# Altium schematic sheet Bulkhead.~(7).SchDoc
size B; Organization: Monterey Bay Aquarium Research Institute; Address1: 7700 Sandholdt Rd; Address2: Moss Landing, CA 95039-9644; CompanyName: MBARI
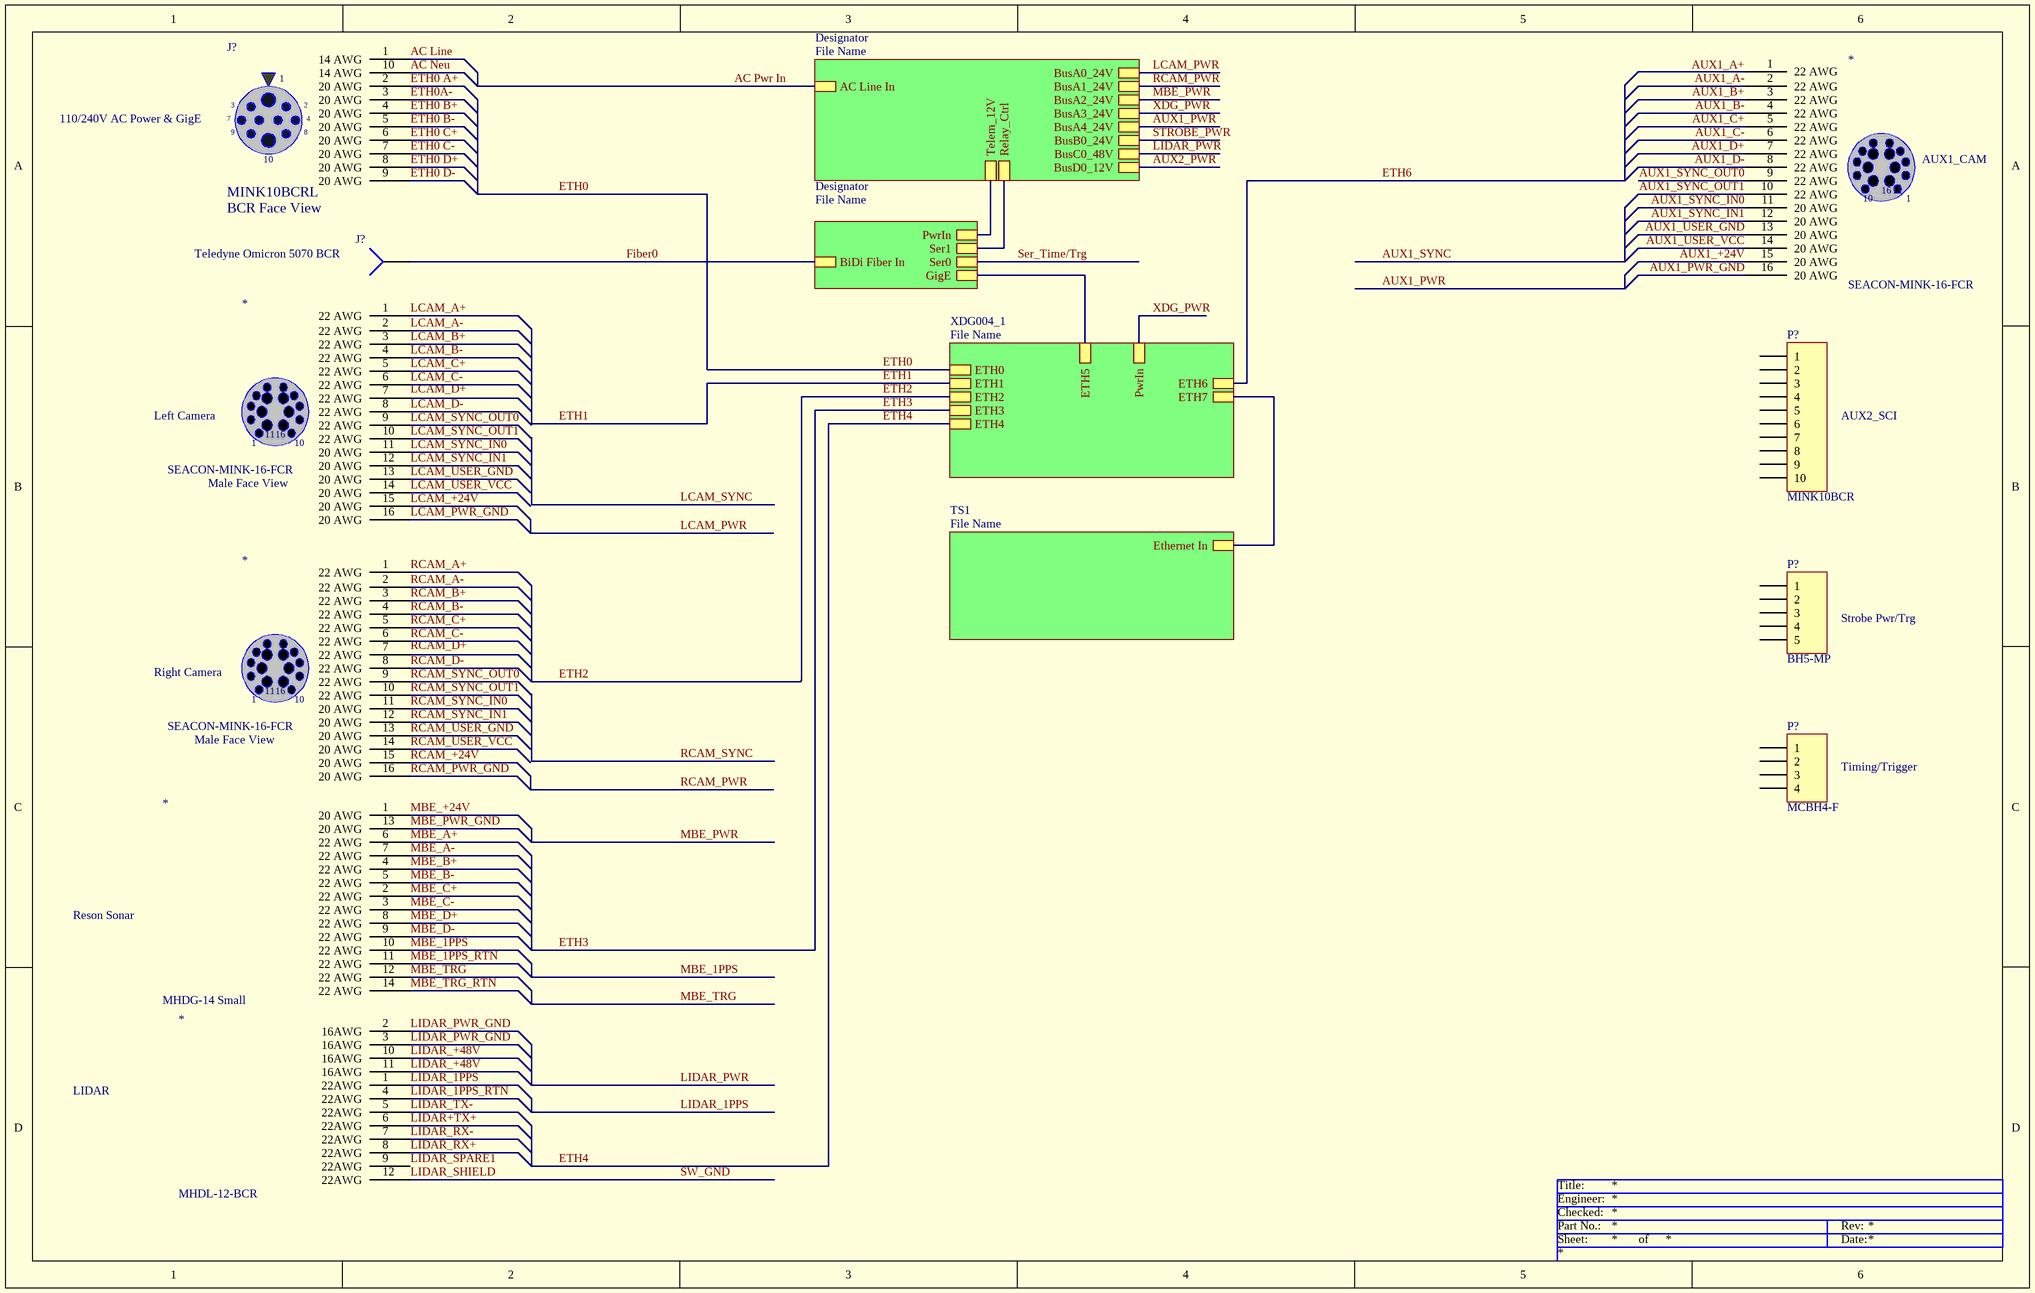
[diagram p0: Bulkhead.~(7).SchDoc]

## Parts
(Parts that share a designator on the sheet are numbered #1, #2 ... from top to bottom, then left to right.)
*#1  SEACON-MINK-16-FCR
*#2  SEACON-MINK-16-FCR
*#3  SEACON-MINK-16-FCR
*#4  MHDG-14 Small
*#5  MHDL-12-BCR
J?#1  MINK10BCRL  View: BCR Face View
J?#2  Teledyne Omicron 5070 BCR  [PIN1]
P?#1  MINK10BCR  [HDR1X10]
P?#2  BH5-MP  [HDR1X5]
P?#3  MCBH4-F  [HDR1X4]

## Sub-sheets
Designator = File Name: AC Line In, BusA0_24V, BusA1_24V, BusC0_48V, BusA2_24V, BusB0_24V, BusD0_12V, BusA3_24V, Telem_12V, Relay_Ctrl, BusA4_24V
Designator = File Name: BiDi Fiber In, GigE, Ser0, Ser1, PwrIn
TS1 = File Name: Ethernet In
XDG004_1 = File Name: ETH0, ETH1, ETH2, ETH3, ETH4, ETH5, ETH6, ETH7, PwrIn

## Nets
AC Line: J?#1.1(14_AWG)
AC Neu: J?#1.10(14_AWG)
AUX1_+24V: *#1.15(20_AWG)
AUX1_A-: *#1.2(22_AWG)
AUX1_B+: *#1.3(22_AWG)
AUX1_B-: *#1.4(22_AWG)
AUX1_C+: *#1.5(22_AWG)
AUX1_C-: *#1.6(22_AWG)
AUX1_D+: *#1.7(22_AWG)
AUX1_D-: *#1.8(22_AWG)
AUX1_PWR_GND: *#1.16(20_AWG)
AUX1_SYNC_IN0: *#1.11(20_AWG)
AUX1_SYNC_IN1: *#1.12(20_AWG)
AUX1_SYNC_OUT0: *#1.9(22_AWG)
AUX1_SYNC_OUT1: *#1.10(22_AWG)
AUX1_USER_GND: *#1.13(20_AWG)
AUX1_USER_VCC: *#1.14(20_AWG)
ETH0 A+: J?#1.2(20_AWG)
ETH0 B+: J?#1.4(20_AWG)
ETH0 B-: J?#1.5(20_AWG)
ETH0 C+: J?#1.6(20_AWG)
ETH0 C-: J?#1.7(20_AWG)
ETH0 D+: J?#1.8(20_AWG)
ETH0 D-: J?#1.9(20_AWG)
ETH0A-: J?#1.3(20_AWG)
Fiber0: J?#2.1 ; sheet Designator/BiDi Fiber In
LCAM_+24V: *#2.15(20_AWG)
LCAM_A+: *#2.1(22_AWG)
LCAM_A-: *#2.2(22_AWG)
LCAM_B+: *#2.3(22_AWG)
LCAM_B-: *#2.4(22_AWG)
LCAM_C+: *#2.5(22_AWG)
LCAM_C-: *#2.6(22_AWG)
LCAM_D-: *#2.8(22_AWG)
LCAM_PWR_GND: *#2.16(20_AWG)
LCAM_SYNC_IN0: *#2.11(20_AWG)
LCAM_SYNC_IN1: *#2.12(20_AWG)
LCAM_SYNC_OUT0: *#2.9(22_AWG)
LCAM_SYNC_OUT1: *#2.10(22_AWG)
LCAM_USER_GND: *#2.13(20_AWG)
LCAM_USER_VCC: *#2.14(20_AWG)
LIDAR+TX+: *#5.6(22AWG)
LIDAR_1PPS: *#5.1(22AWG)
LIDAR_1PPS_RTN: *#5.4(22AWG)
LIDAR_+48V: *#5.10(16AWG) *#5.11(16AWG)
LIDAR_PWR_GND: *#5.2(16AWG) *#5.3(16AWG)
LIDAR_RX+: *#5.8(22AWG)
LIDAR_RX-: *#5.7(22AWG)
LIDAR_SHIELD: *#5.12(22AWG)  [also labelled SW_GND]
LIDAR_SPARE1: *#5.9(22AWG)
LIDAR_TX-: *#5.5(22AWG)
MBE_1PPS: *#4.10(22_AWG)
MBE_1PPS_RTN: *#4.11(22_AWG)
MBE_+24V: *#4.1(20_AWG)
MBE_A+: *#4.6(22_AWG)
MBE_A-: *#4.7(22_AWG)
MBE_B+: *#4.4(22_AWG)
MBE_B-: *#4.5(22_AWG)
MBE_C+: *#4.2(22_AWG)
MBE_C-: *#4.3(22_AWG)
MBE_D+: *#4.8(22_AWG)
MBE_D-: *#4.9(22_AWG)
MBE_PWR_GND: *#4.13(20_AWG)
MBE_TRG: *#4.12(22_AWG)
MBE_TRG_RTN: *#4.14(22_AWG)
RCAM_+24V: *#3.15(20_AWG)
RCAM_A+: *#3.1(22_AWG)
RCAM_A-: *#3.2(22_AWG)
RCAM_B+: *#3.3(22_AWG)
RCAM_B-: *#3.4(22_AWG)
RCAM_C+: *#3.5(22_AWG)
RCAM_C-: *#3.6(22_AWG)
RCAM_D-: *#3.8(22_AWG)
RCAM_PWR_GND: *#3.16(20_AWG)
RCAM_SYNC_IN0: *#3.11(20_AWG)
RCAM_SYNC_IN1: *#3.12(20_AWG)
RCAM_SYNC_OUT0: *#3.9(22_AWG)
RCAM_SYNC_OUT1: *#3.10(22_AWG)
RCAM_USER_GND: *#3.13(20_AWG)
RCAM_USER_VCC: *#3.14(20_AWG)

Not connected (* = marked no-connect by the designer): *#1 1(22_AWG); *#2 7(22_AWG); *#3 7(22_AWG); P?#1 1 2 3 4 5 6 7 8 9 10; P?#2 1 2 3 4 5; P?#3 1 2 3 4

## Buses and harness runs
bus AC Pwr In = sheet Designator/AC Line In
bus AUX1_PWR
bus AUX1_PWR = sheet Designator/BusA4_24V
bus AUX1_SYNC
bus AUX2_PWR = sheet Designator/BusD0_12V
bus ETH0 = sheet XDG004_1/ETH0
bus ETH1 = sheet XDG004_1/ETH1
bus ETH2 = sheet XDG004_1/ETH2
bus ETH3 = sheet XDG004_1/ETH3
bus ETH4 = sheet XDG004_1/ETH4
bus ETH6 = sheet XDG004_1/ETH6
bus LCAM_PWR
bus LCAM_PWR = sheet Designator/BusA0_24V
bus LCAM_SYNC
bus LIDAR_1PPS
bus LIDAR_PWR
bus LIDAR_PWR = sheet Designator/BusC0_48V
bus MBE_1PPS
bus MBE_PWR
bus MBE_PWR = sheet Designator/BusA2_24V
bus MBE_TRG
bus RCAM_PWR
bus RCAM_PWR = sheet Designator/BusA1_24V
bus RCAM_SYNC
bus Ser_Time/Trg = sheet Designator/Ser0
bus sheet Designator/GigE = sheet XDG004_1/ETH5
bus sheet Designator/PwrIn = sheet Designator/Telem_12V
bus sheet Designator/Relay_Ctrl = sheet Designator/Ser1
bus sheet TS1/Ethernet In = sheet XDG004_1/ETH7
bus STROBE_PWR = sheet Designator/BusB0_24V
bus XDG_PWR = sheet Designator/BusA3_24V
bus XDG_PWR = sheet XDG004_1/PwrIn

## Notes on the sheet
- 110/240V AC Power & GigE
- AUX1_CAM
- Left Camera
- AUX2_SCI
- Male Face View
- Strobe Pwr/Trg
- Right Camera
- Timing/Trigger
- Reson Sonar
- LIDAR
- Labels drawn without touching a wire or pin: AUX1_A+, LCAM_D+, RCAM_D+

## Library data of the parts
*#1-*#3 = SEACON-MINK-16-FCR: Seacon MINK-16 FCR
*#5 = MHDL-12-BCR: Impulse MHDL12 BCR
J?#1 = SEACON-MINK-10/L CCR (SMALL): Seacon MINK-10/L-CCR Molded to C/F Falmat Cable
J?#2 = Socket
P?#1 = Header 10: Header, 10-Pin
P?#2 = Header 5: Header, 5-Pin
P?#3 = Header 4: Header, 4-Pin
